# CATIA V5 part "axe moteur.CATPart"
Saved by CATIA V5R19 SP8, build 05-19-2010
Part number: axe moteur
Revision: ANY
Definition: UNKNOWN
Nomenclature: axe moteur
Source: Unknown
Bounding box of the stored display mesh (mm): x -2.889 to 2.111, y -2.343 to 5.113, z -15.98 to -10.98
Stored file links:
  D:\Documents\1_Travail\1 - ac-limoges.fr\ac-limoges.fr\Emmanuel Maynard - STI2D_Turgot\2 -2I2D\2_SEQUENCE_Serrure_Biométrique\5-Spé_ITEC\Serrure_Bio_Eleve\axe moteur.CATPart
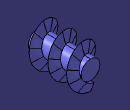
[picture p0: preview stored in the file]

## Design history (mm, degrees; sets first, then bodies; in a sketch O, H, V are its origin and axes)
Body1 "Extrusion2" (main body)
  Solid1: solid without history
